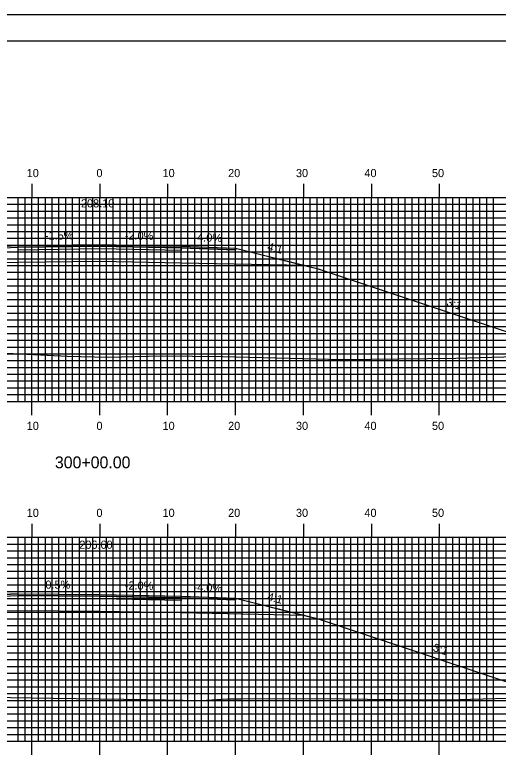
# Model space of a CAD drawing. Extents: x 1815309 to 1815652, y 442591 to 442811.
# Drawn here: x 1815462 to 1815533.2, y 442701.2 to 442810.5 of the extents above; entities that cross this region are included whole.
import ezdxf

# ---------------------------------------------------------------- set-up
doc = ezdxf.new("R2010")
doc.units = 0
for name, color, linetype in [('ANNOTATION', 7, 'Continuous'), ('BORDER', 7, 'Continuous'), ('D_Roadway_Centerline', 7, 'Continuous'), ('D_Roadway_Centerline_Text', 7, 'Continuous'), ('D_Roadway_Edge_Shoulder', 7, 'Continuous'), ('D_Roadway_Edge_TW', 7, 'Continuous'), ('D_Roadway_Pavement', 7, 'Continuous'), ('D_Roadway_SlopeLines', 7, 'Continuous'), ('D_Roadway_SubGrade', 7, 'Continuous'), ('H_V ANNOTATION', 7, 'Continuous'), ('MAJOR', 7, 'Continuous'), ('MINOR', 7, 'Continuous'), ('PLOT BOUNDARY', 7, 'Continuous'), ('S_Roadway_Centerline', 7, 'Continuous')]:
    doc.layers.add(name, color=color, linetype=linetype)

msp = doc.modelspace()

# ---------------------------------------------------------------- linework, layer by layer
at = {"layer": 'BORDER'}
msp.add_lwpolyline([(1815324.93, 442596.67), (1815644.93, 442596.67), (1815644.93, 442806.67), (1815324.93, 442806.67)], close=True, dxfattribs=at)
at = {"layer": 'D_Roadway_Centerline'}
for points in [[(1815411.13, 442762.8), (1815442.53, 442773.27), (1815444.36, 442773.73), (1815454.53, 442776.27), (1815462.53, 442776.59), (1815474.53, 442776.77), (1815486.53, 442776.53), (1815494.53, 442776.21), (1815504.71, 442773.67), (1815506.53, 442773.21), (1815545.26, 442760.3)], [(1815412.84, 442712.11), (1815442.53, 442722.01), (1815444.36, 442722.46), (1815454.53, 442725.01), (1815462.53, 442725.33), (1815474.53, 442725.27), (1815486.53, 442725.03), (1815494.53, 442724.71), (1815504.71, 442722.17), (1815506.53, 442721.71), (1815541.27, 442710.13)]]:
    msp.add_lwpolyline(points, dxfattribs=at)
at = {"layer": 'D_Roadway_Edge_Shoulder'}
for points in [[(1815462.53, 442776.59), (1815454.53, 442776.27), (1815454.53, 442776.02), (1815462.53, 442776.34)], [(1815486.53, 442776.53), (1815494.53, 442776.21), (1815494.53, 442775.96), (1815486.53, 442776.28)], [(1815462.53, 442725.33), (1815454.53, 442725.01), (1815454.53, 442724.76), (1815462.53, 442725.08)], [(1815486.53, 442725.03), (1815494.53, 442724.71), (1815494.53, 442724.46), (1815486.53, 442724.78)]]:
    msp.add_lwpolyline(points, close=True, dxfattribs=at)
at = {"layer": 'D_Roadway_Edge_TW'}
for points in [[(1815462.53, 442776.34), (1815462.53, 442776.59), (1815474.53, 442776.77), (1815486.53, 442776.53), (1815486.53, 442776.28), (1815474.53, 442776.52)], [(1815462.53, 442725.08), (1815462.53, 442725.33), (1815474.53, 442725.27), (1815486.53, 442725.03), (1815486.53, 442724.78), (1815474.53, 442725.02)]]:
    msp.add_lwpolyline(points, close=True, dxfattribs=at)
at = {"layer": 'D_Roadway_Pavement'}
for points in [[(1815462.53, 442775.92), (1815462.53, 442776.34), (1815474.53, 442776.52), (1815486.53, 442776.28), (1815486.53, 442775.86), (1815474.53, 442776.1)], [(1815462.53, 442724.66), (1815462.53, 442725.08), (1815474.53, 442725.02), (1815486.53, 442724.78), (1815486.53, 442724.36), (1815474.53, 442724.6)]]:
    msp.add_lwpolyline(points, close=True, dxfattribs=at)
at = {"layer": 'D_Roadway_SlopeLines'}
for points in [[(1815494.53, 442776.21), (1815506.53, 442773.21), (1815545.26, 442760.3)], [(1815494.53, 442724.71), (1815506.53, 442721.71), (1815541.27, 442710.13)]]:
    msp.add_lwpolyline(points, dxfattribs=at)
at = {"layer": 'D_Roadway_SubGrade'}
for points in [[(1815462.53, 442774.09), (1815444.36, 442773.73), (1815454.53, 442776.27), (1815454.53, 442776.02), (1815462.53, 442776.34), (1815474.53, 442776.52), (1815486.53, 442776.28), (1815494.53, 442775.96), (1815494.53, 442776.21), (1815504.71, 442773.67), (1815486.53, 442774.03), (1815474.53, 442774.27)], [(1815462.53, 442722.83), (1815444.36, 442722.46), (1815454.53, 442725.01), (1815454.53, 442724.76), (1815462.53, 442725.08), (1815474.53, 442725.02), (1815486.53, 442724.78), (1815494.53, 442724.46), (1815494.53, 442724.71), (1815504.71, 442722.17), (1815486.53, 442722.53), (1815474.53, 442722.77)]]:
    msp.add_lwpolyline(points, close=True, dxfattribs=at)
at = {"layer": 'MAJOR'}
for p, q in [((1815464.53, 442785.67), (1815464.53, 442783.67)), ((1815474.53, 442785.67), (1815474.53, 442783.67)), ((1815484.53, 442785.67), (1815484.53, 442783.67)), ((1815494.53, 442785.67), (1815494.53, 442783.67)), ((1815504.53, 442785.67), (1815504.53, 442783.67)), ((1815514.53, 442785.67), (1815514.53, 442783.67)), ((1815524.53, 442785.67), (1815524.53, 442783.67)), ((1815334.53, 442783.67), (1815614.53, 442783.67)), ((1815334.53, 442783.67), (1815614.53, 442783.67)), ((1815464.53, 442753.67), (1815464.53, 442783.67)), ((1815474.53, 442753.67), (1815474.53, 442783.67)), ((1815484.53, 442753.67), (1815484.53, 442783.67)), ((1815494.53, 442753.67), (1815494.53, 442783.67)), ((1815504.53, 442753.67), (1815504.53, 442783.67)), ((1815514.53, 442753.67), (1815514.53, 442783.67)), ((1815524.53, 442753.67), (1815524.53, 442783.67)), ((1815334.53, 442778.67), (1815614.53, 442778.67)), ((1815334.53, 442773.67), (1815614.53, 442773.67)), ((1815334.53, 442768.67), (1815614.53, 442768.67)), ((1815334.53, 442763.67), (1815614.53, 442763.67)), ((1815334.53, 442758.67), (1815614.53, 442758.67)), ((1815334.53, 442753.67), (1815614.53, 442753.67)), ((1815334.53, 442753.67), (1815614.53, 442753.67)), ((1815464.53, 442751.66), (1815464.53, 442753.67)), ((1815474.53, 442751.66), (1815474.53, 442753.67)), ((1815484.53, 442751.66), (1815484.53, 442753.67)), ((1815494.53, 442751.66), (1815494.53, 442753.67)), ((1815504.53, 442751.66), (1815504.53, 442753.67)), ((1815514.53, 442751.66), (1815514.53, 442753.67)), ((1815524.53, 442751.66), (1815524.53, 442753.67)), ((1815464.53, 442735.67), (1815464.53, 442733.67)), ((1815474.53, 442735.67), (1815474.53, 442733.67)), ((1815484.53, 442735.67), (1815484.53, 442733.67)), ((1815494.53, 442735.67), (1815494.53, 442733.67)), ((1815504.53, 442735.67), (1815504.53, 442733.67)), ((1815514.53, 442735.67), (1815514.53, 442733.67)), ((1815524.53, 442735.67), (1815524.53, 442733.67)), ((1815334.53, 442733.67), (1815614.53, 442733.67)), ((1815334.53, 442733.67), (1815614.53, 442733.67)), ((1815464.53, 442703.67), (1815464.53, 442733.67)), ((1815474.53, 442703.67), (1815474.53, 442733.67)), ((1815484.53, 442703.67), (1815484.53, 442733.67)), ((1815494.53, 442703.67), (1815494.53, 442733.67)), ((1815504.53, 442703.67), (1815504.53, 442733.67)), ((1815514.53, 442703.67), (1815514.53, 442733.67)), ((1815524.53, 442703.67), (1815524.53, 442733.67)), ((1815334.53, 442728.67), (1815614.53, 442728.67)), ((1815334.53, 442723.67), (1815614.53, 442723.67)), ((1815334.53, 442718.67), (1815614.53, 442718.67)), ((1815334.53, 442713.67), (1815614.53, 442713.67)), ((1815334.53, 442708.67), (1815614.53, 442708.67)), ((1815334.53, 442703.67), (1815614.53, 442703.67)), ((1815334.53, 442703.67), (1815614.53, 442703.67)), ((1815464.53, 442701.66), (1815464.53, 442703.67)), ((1815474.53, 442701.66), (1815474.53, 442703.67)), ((1815484.53, 442701.66), (1815484.53, 442703.67)), ((1815494.53, 442701.66), (1815494.53, 442703.67)), ((1815504.53, 442701.66), (1815504.53, 442703.67)), ((1815514.53, 442701.66), (1815514.53, 442703.67)), ((1815524.53, 442701.66), (1815524.53, 442703.67))]:
    msp.add_line(p, q, dxfattribs=at)
at = {"layer": 'MINOR'}
for p, q in [((1815462.53, 442753.67), (1815462.53, 442783.67)), ((1815463.53, 442753.67), (1815463.53, 442783.67)), ((1815465.53, 442753.67), (1815465.53, 442783.67)), ((1815466.53, 442753.67), (1815466.53, 442783.67)), ((1815467.53, 442753.67), (1815467.53, 442783.67)), ((1815468.53, 442753.67), (1815468.53, 442783.67)), ((1815469.53, 442753.67), (1815469.53, 442783.67)), ((1815470.53, 442753.67), (1815470.53, 442783.67)), ((1815471.53, 442753.67), (1815471.53, 442783.67)), ((1815472.53, 442753.67), (1815472.53, 442783.67)), ((1815473.53, 442753.67), (1815473.53, 442783.67)), ((1815475.53, 442753.67), (1815475.53, 442783.67)), ((1815476.53, 442753.67), (1815476.53, 442783.67)), ((1815477.53, 442753.67), (1815477.53, 442783.67)), ((1815478.53, 442753.67), (1815478.53, 442783.67)), ((1815479.53, 442753.67), (1815479.53, 442783.67)), ((1815480.53, 442753.67), (1815480.53, 442783.67)), ((1815481.53, 442753.67), (1815481.53, 442783.67)), ((1815482.53, 442753.67), (1815482.53, 442783.67)), ((1815483.53, 442753.67), (1815483.53, 442783.67)), ((1815485.53, 442753.67), (1815485.53, 442783.67)), ((1815486.53, 442753.67), (1815486.53, 442783.67)), ((1815487.53, 442753.67), (1815487.53, 442783.67)), ((1815488.53, 442753.67), (1815488.53, 442783.67)), ((1815489.53, 442753.67), (1815489.53, 442783.67)), ((1815490.53, 442753.67), (1815490.53, 442783.67)), ((1815491.53, 442753.67), (1815491.53, 442783.67)), ((1815492.53, 442753.67), (1815492.53, 442783.67)), ((1815493.53, 442753.67), (1815493.53, 442783.67)), ((1815495.53, 442753.67), (1815495.53, 442783.67)), ((1815496.53, 442753.67), (1815496.53, 442783.67)), ((1815497.53, 442753.67), (1815497.53, 442783.67)), ((1815498.53, 442753.67), (1815498.53, 442783.67)), ((1815499.53, 442753.67), (1815499.53, 442783.67)), ((1815500.53, 442753.67), (1815500.53, 442783.67)), ((1815501.53, 442753.67), (1815501.53, 442783.67)), ((1815502.53, 442753.67), (1815502.53, 442783.67)), ((1815503.53, 442753.67), (1815503.53, 442783.67)), ((1815505.53, 442753.67), (1815505.53, 442783.67)), ((1815506.53, 442753.67), (1815506.53, 442783.67)), ((1815507.53, 442753.67), (1815507.53, 442783.67)), ((1815508.53, 442753.67), (1815508.53, 442783.67)), ((1815509.53, 442753.67), (1815509.53, 442783.67)), ((1815510.53, 442753.67), (1815510.53, 442783.67)), ((1815511.53, 442753.67), (1815511.53, 442783.67)), ((1815512.53, 442753.67), (1815512.53, 442783.67)), ((1815513.53, 442753.67), (1815513.53, 442783.67)), ((1815515.53, 442753.67), (1815515.53, 442783.67)), ((1815516.53, 442753.67), (1815516.53, 442783.67)), ((1815517.53, 442753.67), (1815517.53, 442783.67)), ((1815518.53, 442753.67), (1815518.53, 442783.67)), ((1815519.53, 442753.67), (1815519.53, 442783.67)), ((1815520.53, 442753.67), (1815520.53, 442783.67)), ((1815521.53, 442753.67), (1815521.53, 442783.67)), ((1815522.53, 442753.67), (1815522.53, 442783.67)), ((1815523.53, 442753.67), (1815523.53, 442783.67)), ((1815525.53, 442753.67), (1815525.53, 442783.67)), ((1815526.53, 442753.67), (1815526.53, 442783.67)), ((1815527.53, 442753.67), (1815527.53, 442783.67)), ((1815528.53, 442753.67), (1815528.53, 442783.67)), ((1815529.53, 442753.67), (1815529.53, 442783.67)), ((1815530.53, 442753.67), (1815530.53, 442783.67)), ((1815531.53, 442753.67), (1815531.53, 442783.67)), ((1815532.53, 442753.67), (1815532.53, 442783.67)), ((1815334.53, 442782.67), (1815614.53, 442782.67)), ((1815334.53, 442781.67), (1815614.53, 442781.67)), ((1815334.53, 442780.67), (1815614.53, 442780.67)), ((1815334.53, 442779.67), (1815614.53, 442779.67)), ((1815334.53, 442777.67), (1815614.53, 442777.67)), ((1815334.53, 442776.67), (1815614.53, 442776.67)), ((1815334.53, 442775.67), (1815614.53, 442775.67)), ((1815334.53, 442774.67), (1815614.53, 442774.67)), ((1815334.53, 442772.67), (1815614.53, 442772.67)), ((1815334.53, 442771.67), (1815614.53, 442771.67)), ((1815334.53, 442770.67), (1815614.53, 442770.67)), ((1815334.53, 442769.67), (1815614.53, 442769.67)), ((1815334.53, 442767.67), (1815614.53, 442767.67)), ((1815334.53, 442766.67), (1815614.53, 442766.67)), ((1815334.53, 442765.67), (1815614.53, 442765.67)), ((1815334.53, 442764.67), (1815614.53, 442764.67)), ((1815334.53, 442762.67), (1815614.53, 442762.67)), ((1815334.53, 442761.67), (1815614.53, 442761.67)), ((1815334.53, 442760.67), (1815614.53, 442760.67)), ((1815334.53, 442759.67), (1815614.53, 442759.67)), ((1815334.53, 442757.67), (1815614.53, 442757.67)), ((1815334.53, 442756.67), (1815614.53, 442756.67)), ((1815334.53, 442755.67), (1815614.53, 442755.67)), ((1815334.53, 442754.67), (1815614.53, 442754.67)), ((1815462.53, 442703.67), (1815462.53, 442733.67)), ((1815463.53, 442703.67), (1815463.53, 442733.67)), ((1815465.53, 442703.67), (1815465.53, 442733.67)), ((1815466.53, 442703.67), (1815466.53, 442733.67)), ((1815467.53, 442703.67), (1815467.53, 442733.67)), ((1815468.53, 442703.67), (1815468.53, 442733.67)), ((1815469.53, 442703.67), (1815469.53, 442733.67)), ((1815470.53, 442703.67), (1815470.53, 442733.67)), ((1815471.53, 442703.67), (1815471.53, 442733.67)), ((1815472.53, 442703.67), (1815472.53, 442733.67)), ((1815473.53, 442703.67), (1815473.53, 442733.67)), ((1815475.53, 442703.67), (1815475.53, 442733.67)), ((1815476.53, 442703.67), (1815476.53, 442733.67)), ((1815477.53, 442703.67), (1815477.53, 442733.67)), ((1815478.53, 442703.67), (1815478.53, 442733.67)), ((1815479.53, 442703.67), (1815479.53, 442733.67)), ((1815480.53, 442703.67), (1815480.53, 442733.67)), ((1815481.53, 442703.67), (1815481.53, 442733.67)), ((1815482.53, 442703.67), (1815482.53, 442733.67)), ((1815483.53, 442703.67), (1815483.53, 442733.67)), ((1815485.53, 442703.67), (1815485.53, 442733.67)), ((1815486.53, 442703.67), (1815486.53, 442733.67)), ((1815487.53, 442703.67), (1815487.53, 442733.67)), ((1815488.53, 442703.67), (1815488.53, 442733.67)), ((1815489.53, 442703.67), (1815489.53, 442733.67)), ((1815490.53, 442703.67), (1815490.53, 442733.67)), ((1815491.53, 442703.67), (1815491.53, 442733.67)), ((1815492.53, 442703.67), (1815492.53, 442733.67)), ((1815493.53, 442703.67), (1815493.53, 442733.67)), ((1815495.53, 442703.67), (1815495.53, 442733.67)), ((1815496.53, 442703.67), (1815496.53, 442733.67)), ((1815497.53, 442703.67), (1815497.53, 442733.67)), ((1815498.53, 442703.67), (1815498.53, 442733.67)), ((1815499.53, 442703.67), (1815499.53, 442733.67)), ((1815500.53, 442703.67), (1815500.53, 442733.67)), ((1815501.53, 442703.67), (1815501.53, 442733.67)), ((1815502.53, 442703.67), (1815502.53, 442733.67)), ((1815503.53, 442703.67), (1815503.53, 442733.67)), ((1815505.53, 442703.67), (1815505.53, 442733.67)), ((1815506.53, 442703.67), (1815506.53, 442733.67)), ((1815507.53, 442703.67), (1815507.53, 442733.67)), ((1815508.53, 442703.67), (1815508.53, 442733.67)), ((1815509.53, 442703.67), (1815509.53, 442733.67)), ((1815510.53, 442703.67), (1815510.53, 442733.67)), ((1815511.53, 442703.67), (1815511.53, 442733.67)), ((1815512.53, 442703.67), (1815512.53, 442733.67)), ((1815513.53, 442703.67), (1815513.53, 442733.67)), ((1815515.53, 442703.67), (1815515.53, 442733.67)), ((1815516.53, 442703.67), (1815516.53, 442733.67)), ((1815517.53, 442703.67), (1815517.53, 442733.67)), ((1815518.53, 442703.67), (1815518.53, 442733.67)), ((1815519.53, 442703.67), (1815519.53, 442733.67)), ((1815520.53, 442703.67), (1815520.53, 442733.67)), ((1815521.53, 442703.67), (1815521.53, 442733.67)), ((1815522.53, 442703.67), (1815522.53, 442733.67)), ((1815523.53, 442703.67), (1815523.53, 442733.67)), ((1815525.53, 442703.67), (1815525.53, 442733.67)), ((1815526.53, 442703.67), (1815526.53, 442733.67)), ((1815527.53, 442703.67), (1815527.53, 442733.67)), ((1815528.53, 442703.67), (1815528.53, 442733.67)), ((1815529.53, 442703.67), (1815529.53, 442733.67)), ((1815530.53, 442703.67), (1815530.53, 442733.67)), ((1815531.53, 442703.67), (1815531.53, 442733.67)), ((1815532.53, 442703.67), (1815532.53, 442733.67)), ((1815334.53, 442732.67), (1815614.53, 442732.67)), ((1815334.53, 442731.67), (1815614.53, 442731.67)), ((1815334.53, 442730.67), (1815614.53, 442730.67)), ((1815334.53, 442729.67), (1815614.53, 442729.67)), ((1815334.53, 442727.67), (1815614.53, 442727.67)), ((1815334.53, 442726.67), (1815614.53, 442726.67)), ((1815334.53, 442725.67), (1815614.53, 442725.67)), ((1815334.53, 442724.67), (1815614.53, 442724.67)), ((1815334.53, 442722.67), (1815614.53, 442722.67)), ((1815334.53, 442721.67), (1815614.53, 442721.67)), ((1815334.53, 442720.67), (1815614.53, 442720.67)), ((1815334.53, 442719.67), (1815614.53, 442719.67)), ((1815334.53, 442717.67), (1815614.53, 442717.67)), ((1815334.53, 442716.67), (1815614.53, 442716.67)), ((1815334.53, 442715.67), (1815614.53, 442715.67)), ((1815334.53, 442714.67), (1815614.53, 442714.67)), ((1815334.53, 442712.67), (1815614.53, 442712.67)), ((1815334.53, 442711.67), (1815614.53, 442711.67)), ((1815334.53, 442710.67), (1815614.53, 442710.67)), ((1815334.53, 442709.67), (1815614.53, 442709.67)), ((1815334.53, 442707.67), (1815614.53, 442707.67)), ((1815334.53, 442706.67), (1815614.53, 442706.67)), ((1815334.53, 442705.67), (1815614.53, 442705.67)), ((1815334.53, 442704.67), (1815614.53, 442704.67))]:
    msp.add_line(p, q, dxfattribs=at)
at = {"layer": 'PLOT BOUNDARY'}
msp.add_lwpolyline([(1815308.75, 442590.55), (1815648.75, 442590.55), (1815648.75, 442810.55), (1815308.75, 442810.55)], close=True, dxfattribs=at)
at = {"layer": 'S_Roadway_Centerline'}
for points in [[(1815393.38, 442763.44), (1815408.3, 442762.88), (1815416.89, 442762.65), (1815425.21, 442762.19), (1815430.38, 442761.94), (1815442.38, 442761.3), (1815443.99, 442761.22), (1815450.92, 442761.05), (1815457.13, 442760.91), (1815458.74, 442760.88), (1815469.81, 442760.34), (1815475.74, 442760.17), (1815483.72, 442760.39), (1815492.68, 442760.29), (1815496.59, 442760.17), (1815510.25, 442759.81), (1815526.98, 442760.01), (1815537.6, 442760.33)], [(1815404.5, 442712.5), (1815409.44, 442712.19), (1815421.82, 442711.9), (1815434.24, 442711.27), (1815437.61, 442711.07), (1815439.81, 442710.91), (1815449.64, 442710.43), (1815454.09, 442710.17), (1815455.05, 442710.17), (1815467.67, 442710.02), (1815471.06, 442709.93), (1815481.55, 442709.82), (1815489.45, 442709.66), (1815493.35, 442709.88), (1815495.31, 442709.91), (1815506.57, 442709.97), (1815517.69, 442709.81), (1815523.52, 442709.73), (1815525.6, 442709.76), (1815539.97, 442710.15)]]:
    msp.add_lwpolyline(points, dxfattribs=at)

# ---------------------------------------------------------------- texts
at = {"layer": 'ANNOTATION'}
for s, rotation, p in [('-1.5%', 0.8515, (1815466.47, 442777.45)), ('-2.0%', 358.8542, (1815478.22, 442777.5)), ('-4.0%', 357.7094, (1815488.33, 442777.26)), ('4:1', 345.9638, (1815499.13, 442775.92)), ('3:1', 341.5652, (1815525.5, 442767.79)), ('0.5%', 359.7281, (1815466.53, 442726.11)), ('-2.0%', 358.8542, (1815478.22, 442726)), ('-4.0%', 357.7094, (1815488.33, 442725.76)), ('4:1', 345.9638, (1815499.13, 442724.42)), ('3:1', 341.5652, (1815523.5, 442716.96))]:
    msp.add_text(s, height=1.2, rotation=rotation, dxfattribs=at).set_placement(p)
at = {"layer": 'D_Roadway_Centerline'}
for s, p in [('C', (1815474.53, 442776.77)), ('L', (1815474.53, 442776.76)), ('C', (1815474.53, 442725.27)), ('L', (1815474.53, 442725.26))]:
    msp.add_text(s, height=0.0146, dxfattribs=at).set_placement(p)
at = {"layer": 'D_Roadway_Centerline_Text'}
for s, p in [('208.10', (1815471.77, 442782.21)), ('206.60', (1815471.52, 442731.98))]:
    msp.add_text(s, height=1.2, dxfattribs=at).set_placement(p)
at = {"layer": 'H_V ANNOTATION'}
for s, height, p in [('10', 1.2, (1815463.78, 442786.67)), ('0', 1.2, (1815474.05, 442786.67)), ('10', 1.2, (1815483.78, 442786.67)), ('20', 1.2, (1815493.44, 442786.67)), ('30', 1.2, (1815503.43, 442786.67)), ('40', 1.2, (1815513.51, 442786.67)), ('50', 1.2, (1815523.46, 442786.67)), ('10', 1.2, (1815463.78, 442749.47)), ('0', 1.2, (1815474.05, 442749.47)), ('10', 1.2, (1815483.78, 442749.47)), ('20', 1.2, (1815493.44, 442749.47)), ('30', 1.2, (1815503.43, 442749.47)), ('40', 1.2, (1815513.51, 442749.47)), ('50', 1.2, (1815523.46, 442749.47)), ('300+00.00', 1.75, (1815467.93, 442743.82)), ('10', 1.2, (1815463.78, 442736.67)), ('0', 1.2, (1815474.05, 442736.67)), ('10', 1.2, (1815483.78, 442736.67)), ('20', 1.2, (1815493.44, 442736.67)), ('30', 1.2, (1815503.43, 442736.67)), ('40', 1.2, (1815513.51, 442736.67)), ('50', 1.2, (1815523.46, 442736.67))]:
    msp.add_text(s, height=height, dxfattribs=at).set_placement(p)

doc.saveas('drawing.dxf')
